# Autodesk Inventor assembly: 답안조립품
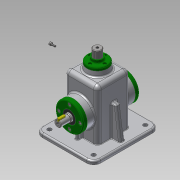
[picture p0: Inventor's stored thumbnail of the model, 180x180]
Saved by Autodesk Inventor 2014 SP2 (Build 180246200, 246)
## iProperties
Created: 2016-08
Part Number: 답안조립품
Document SubType Name: Assembly
Designer: user
Author: user
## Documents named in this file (17)
- C:\Users\user\Desktop\460820V1007\답안조립품.iam
- C:\Users\user\Desktop\460820V1007\본체.ipt
- C:\Users\user\Desktop\460820V1007\뒤커버.ipt
- C:\Users\user\Desktop\460820V1007\앞커버.ipt
- C:\Users\user\Desktop\460820V1007\상부부시.ipt
- C:\Users\user\Desktop\460820V1007\베어링 15 x 35 x 11.ipt
- C:\Users\user\Desktop\460820V1007\오일실 15 25 7.ipt
- C:\Users\user\Desktop\460820V1007\편심축.ipt
- C:\Users\user\Desktop\460820V1007\키 5 x 5 x 14.ipt
- C:\Users\user\Desktop\460820V1007\링크.ipt
- C:\Users\user\Desktop\460820V1007\슬라이드바.ipt
- C:\Users\user\Desktop\460820V1007\V-벨트풀리.ipt
- C:\Users\user\Desktop\460820V1007\고정핀.ipt
- C:\Users\user\Desktop\460820V1007\멈춤링 6 x 5.ipt
- C:\Users\user\Desktop\460820V1007\멈춤링 15 x 1.ipt
- C:\Users\user\Desktop\460820V1007\볼트 M4 x 10.ipt
- C:\Users\user\Desktop\460820V1007\볼트 M3 x 8.ipt
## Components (11 placed, 4 different names)
1. V-벨트풀리:1 — 각도:1
2. 고정핀:1 — 강체:1, 강체:5, 강체:2
3. ISO 4762 M3 x 8:1
4. ISO 4762 M4 x 10:1 — 강체:6
5. ISO 4762 M4 x 10:2 — 강체:7
6. ISO 4762 M4 x 10:3
7. ISO 4762 M4 x 10:4
8. ISO 4762 M4 x 10:5
9. ISO 4762 M4 x 10:6
10. ISO 4762 M4 x 10:7
11. ISO 4762 M4 x 10:8
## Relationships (6: WeldJoint 5, Angle 1)
- 강체:1 [WeldJoint]: 고정핀:1
- 강체:5 [WeldJoint]: 고정핀:1
- 강체:2 [WeldJoint]: 고정핀:1
- 각도:1 [Angle]: V-벨트풀리:1
- 강체:6 [WeldJoint]: ISO 4762 M4 x 10:1
- 강체:7 [WeldJoint]: ISO 4762 M4 x 10:2
